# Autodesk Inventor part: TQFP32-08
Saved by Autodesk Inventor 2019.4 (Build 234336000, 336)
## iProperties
Created: 2021-02
Part Number: TQFP32-08
Material: Generic
Document SubType Name: Modeling
Designer: Administrator
Density: 1 g/cm^3
Appearance: Default
Title: TQFP32-08
Author: Administrator
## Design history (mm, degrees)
feature "Body1"
body "Solid1"
